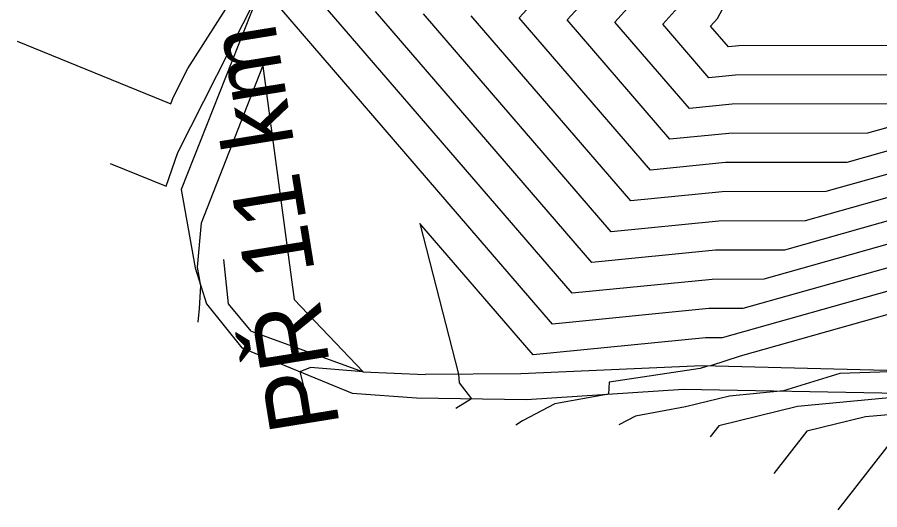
# Model space of a CAD drawing. Extents: x -549394 to -546608, y -1037055 to -1033629.
# Drawn here: x -548278 to -548165.9, y -1035727 to -1035663.1 of the extents above; entities that cross this region are included whole.
import ezdxf

# ---------------------------------------------------------------- set-up
doc = ezdxf.new("R2010")
doc.units = 0
for name, color, linetype in [('hlavni_vrst', 7, 'Continuous'), ('hrana_L', 7, 'Continuous'), ('norm_vrst', 7, 'Continuous'), ('x_popis_pricne_rezy_C1', 7, 'Continuous')]:
    doc.layers.add(name, color=color, linetype=linetype)

msp = doc.modelspace()

# ---------------------------------------------------------------- linework, layer by layer
at = {"layer": 'hlavni_vrst'}
for p, q in [((-548255.82, -1035669.78), (-548247.58, -1035656.85)), ((-548194.11, -1035664.01), (-548191.78, -1035661.43)), ((-548200.81, -1035690.94), (-548225.2, -1035662.65)), ((-548188.12, -1035670.96), (-548194.11, -1035664.01)), ((-548277.96, -1035666.22), (-548258.01, -1035674.36)), ((-548257.72, -1035673.54), (-548255.82, -1035669.78)), ((-548184.68, -1035670.62), (-548188.12, -1035670.96)), ((-548162.15, -1035670.57), (-548184.68, -1035670.62)), ((-548258.01, -1035674.36), (-548257.72, -1035673.54)), ((-548125.54, -1035675.43), (-548175.62, -1035689.53)), ((-548110.96, -1035686.49), (-548184.07, -1035707.08)), ((-548186.84, -1035689.56), (-548200.81, -1035690.94)), ((-548175.62, -1035689.53), (-548186.84, -1035689.56)), ((-548184.07, -1035707.08), (-548187.93, -1035708.37)), ((-548189.25, -1035708.68), (-548201.07, -1035710.46)), ((-548188.29, -1035708.38), (-548189.25, -1035708.68)), ((-548187.93, -1035708.37), (-548188.29, -1035708.38)), ((-548201.07, -1035710.46), (-548201.16, -1035712.01)), ((-548201.16, -1035712.01), (-548208.15, -1035713.27)), ((-548208.15, -1035713.27), (-548212.35, -1035715.5)), ((-548212.35, -1035715.5), (-548213.19, -1035716.03))]:
    msp.add_line(p, q, dxfattribs=at)
at = {"layer": 'hrana_L'}
for p, q in [((-548246.73, -1035660.38), (-548256.67, -1035685.46)), ((-548256.67, -1035685.46), (-548254.85, -1035695.64)), ((-548250.51, -1035700.32), (-548251.12, -1035694.53)), ((-548254.85, -1035695.64), (-548253.39, -1035700.3)), ((-548253.39, -1035700.3), (-548248.78, -1035706.03)), ((-548247.58, -1035703.85), (-548250.51, -1035700.32)), ((-548247.58, -1035703.85), (-548233.05, -1035709.12)), ((-548248.78, -1035706.03), (-548234.44, -1035711.9)), ((-548188.98, -1035708.34), (-548212.53, -1035709.4)), ((-548108.04, -1035710.38), (-548188.98, -1035708.34)), ((-548233.05, -1035709.12), (-548224.96, -1035709.46)), ((-548212.53, -1035709.4), (-548224.96, -1035709.46)), ((-548234.44, -1035711.9), (-548226.09, -1035712.52)), ((-548211.82, -1035712.72), (-548191.42, -1035711.36)), ((-548191.42, -1035711.36), (-548106.96, -1035713)), ((-548226.09, -1035712.52), (-548211.82, -1035712.72))]:
    msp.add_line(p, q, dxfattribs=at)
at = {"layer": 'norm_vrst'}
for p, q in [((-548212.77, -1035663.2), (-548206.14, -1035655.88)), ((-548206.55, -1035663.47), (-548201.35, -1035657.73)), ((-548200.33, -1035663.74), (-548196.57, -1035659.58)), ((-548257.09, -1035680.68), (-548246.91, -1035660.56)), ((-548187, -1035663.28), (-548185.6, -1035660.56)), ((-548208.42, -1035702.93), (-548243.86, -1035661.84)), ((-548205.88, -1035698.93), (-548237.64, -1035662.11)), ((-548203.34, -1035694.94), (-548231.42, -1035662.38)), ((-548198.27, -1035686.94), (-548218.99, -1035662.92)), ((-548195.73, -1035682.95), (-548212.77, -1035663.2)), ((-548193.19, -1035678.95), (-548206.55, -1035663.47)), ((-548190.65, -1035674.96), (-548200.33, -1035663.74)), ((-548187.9, -1035664.28), (-548187, -1035663.28)), ((-548185.58, -1035666.97), (-548187.9, -1035664.28)), ((-548184.25, -1035666.84), (-548185.58, -1035666.97)), ((-548159.46, -1035666.78), (-548184.25, -1035666.84)), ((-548254.02, -1035689.8), (-548246.08, -1035669.47)), ((-548246.08, -1035669.47), (-548241.98, -1035699.75)), ((-548134.28, -1035668.79), (-548167.54, -1035678.16)), ((-548131.37, -1035671), (-548170.23, -1035681.95)), ((-548128.45, -1035673.22), (-548172.93, -1035685.74)), ((-548185.11, -1035674.41), (-548190.65, -1035674.96)), ((-548164.85, -1035674.36), (-548185.11, -1035674.41)), ((-548185.55, -1035678.2), (-548193.19, -1035678.95)), ((-548167.54, -1035678.16), (-548185.55, -1035678.2)), ((-548122.62, -1035677.64), (-548178.31, -1035693.32)), ((-548258.63, -1035685.04), (-548257.09, -1035680.68)), ((-548119.7, -1035679.85), (-548181.01, -1035697.12)), ((-548265.87, -1035682.08), (-548258.63, -1035685.04)), ((-548185.98, -1035681.98), (-548195.73, -1035682.95)), ((-548170.23, -1035681.95), (-548185.98, -1035681.98)), ((-548116.79, -1035682.07), (-548183.7, -1035700.91)), ((-548113.87, -1035684.28), (-548186.39, -1035704.7)), ((-548186.41, -1035685.77), (-548198.27, -1035686.94)), ((-548172.93, -1035685.74), (-548186.41, -1035685.77)), ((-548254.56, -1035695.55), (-548254.02, -1035689.8)), ((-548210.96, -1035706.92), (-548225.67, -1035689.86)), ((-548225.67, -1035689.86), (-548220.64, -1035709.44)), ((-548187.27, -1035693.34), (-548203.34, -1035694.94)), ((-548178.31, -1035693.32), (-548187.27, -1035693.34)), ((-548254.12, -1035697.97), (-548254.56, -1035695.55)), ((-548187.7, -1035697.13), (-548205.88, -1035698.93)), ((-548181.01, -1035697.12), (-548187.7, -1035697.13)), ((-548254.3, -1035700.9), (-548254.12, -1035697.97)), ((-548241.98, -1035699.75), (-548233.05, -1035709.12)), ((-548254.47, -1035702.69), (-548254.3, -1035700.9)), ((-548188.13, -1035700.92), (-548208.42, -1035702.93)), ((-548183.7, -1035700.91), (-548188.13, -1035700.92)), ((-548188.57, -1035704.7), (-548210.96, -1035706.92)), ((-548186.39, -1035704.7), (-548188.57, -1035704.7)), ((-548239.87, -1035708.58), (-548241.25, -1035709.11)), ((-548233.05, -1035709.12), (-548239.87, -1035708.58)), ((-548241.25, -1035709.11), (-548240.38, -1035712.53)), ((-548233.05, -1035709.12), (-548233.05, -1035709.12)), ((-548233.05, -1035709.12), (-548233.05, -1035709.12)), ((-548233.05, -1035709.12), (-548233.05, -1035709.12)), ((-548220.64, -1035709.44), (-548220.54, -1035710.56)), ((-548171.13, -1035709.35), (-548178.43, -1035711.61)), ((-548161.56, -1035709.03), (-548171.13, -1035709.35)), ((-548220.54, -1035710.56), (-548218.96, -1035712.62)), ((-548178.43, -1035711.61), (-548185.43, -1035712.28)), ((-548159.32, -1035711.98), (-548176.61, -1035713.63)), ((-548218.96, -1035712.62), (-548221.01, -1035713.9)), ((-548185.43, -1035712.28), (-548191.18, -1035713.68)), ((-548140.21, -1035712.35), (-548167.79, -1035714.98)), ((-548191.18, -1035713.68), (-548197.66, -1035714.86)), ((-548176.61, -1035713.63), (-548186.83, -1035716.13)), ((-548197.66, -1035714.86), (-548199.84, -1035716.01)), ((-548167.79, -1035714.98), (-548175.4, -1035716.84)), ((-548186.83, -1035716.13), (-548187.97, -1035717.57)), ((-548175.4, -1035716.84), (-548179.68, -1035722.3)), ((-548163.97, -1035717.56), (-548171.39, -1035727.02))]:
    msp.add_line(p, q, dxfattribs=at)

# ---------------------------------------------------------------- texts
at = {"layer": 'x_popis_pricne_rezy_C1'}
msp.add_text('PŘ 11 km 1.0000', height=9.0627, rotation=99.1956, dxfattribs=at).set_placement((-548236.04, -1035716.11))

doc.saveas('drawing.dxf')
